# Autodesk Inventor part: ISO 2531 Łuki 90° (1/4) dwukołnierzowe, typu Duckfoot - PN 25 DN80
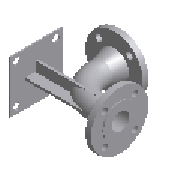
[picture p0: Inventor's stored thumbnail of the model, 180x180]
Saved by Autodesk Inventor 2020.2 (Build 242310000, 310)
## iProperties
Manager: www.cadconsulting.pl
Company: Fabian Stasiak CAD Consulting
IsCustomPart: 0
NAME: PIPING: ISO 2531 90 Deg Double Flanged Duckfoot Bend - PN 25
DATA: <meta><inlinegroups number="0" deflen="0"></inlinegroups><connections number="2"></connections><angles><a>1.5707963267949</a></angles></meta>
Created: 2014-02
Part Number: ISO 2531 Łuki 90° (1/4) dwukołnierzowe, typu Duckfoot - PN 25 DN80
Material: Żeliwo sferoidalne
Description: Rury, łączniki, akcesoria z żeliwa sferoidalnego i ich złącza do zastosowań w instalacjach wodnych lub gazowych - Łuki 90o (1/4) dwukołnierzowe, typu Duckfoot -
Document SubType Name: Modeling
Standard: ISO 2531
Designer: F.Stasiak
Standard Revision: Fifth edition 1998-08-15
Standards Organization: ISO
Language: pl-PL
Size Designation: DN80
Categories: <MemberInstance><Categories><Category DisplayName="Rury cienko- i grubościenne" InternalName="4347fa0f-2144-441d-94cd-e3e15c92b736" Mnemonic="TUBEANDPIPE"><Cate
Density: 7.15 g/cm^3
Appearance: Ciemnoszary
Catalog Web Link: www.expertbooks.pl
Author: F.Stasiak
Subject: Zbiór ćwiczeń. Autodesk Inventor 2020. Kurs Professional
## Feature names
1. Revolution1
2. Sweep1
3. Revolution2
4. Extrusion1
5. Circular Pattern1
6. Extrusion2
7. Circular Pattern2
8. Extrusion3
9. Extrusion4
10. Extrusion5
11. Circular Pattern3
12. Mirror1
13. Sweep2
## Parameters: L2 = 19 mm, f1 = 3 mm, d11 = 132 mm, e = 7 mm, L = 165 mm, C7 = 19 mm, d2 = 7 mm, d3 = 132 mm, d4 = 3 mm, d5 = 15 deg, d15 = 90 deg, d8 = 165 mm, d9 = 7 mm, d10 = 3 mm, d13 = 132 mm, d18 = 7 mm, d19 = 0, d27 = 90 deg, d21 = 16 mm, d22 = 0, d24 = 360 deg, d26 = 16 mm, d28 = 0, d30 = 360 deg, d31 = 19 mm, d32 = 19 mm, d36 = 3.5 mm, d38 = 0, d39 = 7 mm, d41 = 0, d42 = 3.5 mm, d43 = -162 mm, d44 = 19 mm, d45 = 19 mm, d46 = 19 mm, d47 = 3.5 mm, d48 = 0, d50 = 360 deg, d51 = 47 mm, d91 = 1 mm, d52 = 7 mm, d55 = 0, d56 = 19 mm, d57 = 22.5 deg, d58 = 19 mm, d59 = 22.5 deg, d101 = 0, d102 = 0, Size_Designation = 12.345 mm
